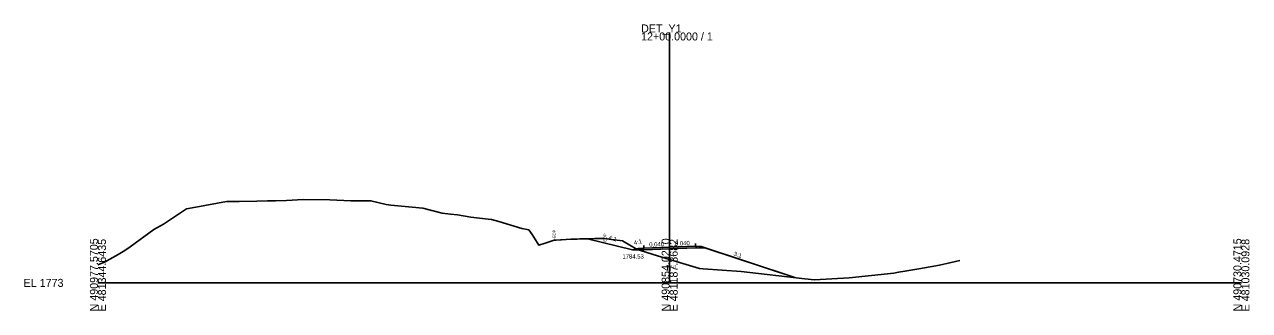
# Model space of a CAD drawing. Extents: x -26 to 403, y -10 to 3149.
# Drawn here: x -25.7 to 402.8, y 1990.3 to 2090.6 of the extents above; entities that cross this region are included whole.
import ezdxf

# ---------------------------------------------------------------- set-up
doc = ezdxf.new("R2010")
doc.units = 0
for name, color, linetype in [('Exist Cross Section Cell', 7, 'Continuous'), ('Exist XS Center Line Elevation Label', 7, 'Continuous'), ('Exist XS Ground Line', 7, 'Continuous'), ('Prop XS Ditch Slope Text', 7, 'Continuous'), ('Prop XS Ditch Standard Text', 7, 'Continuous'), ('Prop XS Dump Level', 7, 'Continuous'), ('Prop XS EOT Tick Mark', 7, 'Continuous'), ('Prop XS Finish Grade', 7, 'Continuous'), ('Prop XS Finish Grade Earthwork', 7, 'Continuous'), ('Prop XS Finish Grade Pavement', 7, 'Continuous'), ('Prop XS Pvmt Edge Slope', 7, 'Continuous'), ('Prop XS SE Text', 7, 'Continuous'), ('Prop XS Side Slope Text', 7, 'Continuous'), ('Prop XS Subgrade Earthwork', 7, 'Continuous'), ('Scratch_Level_3', 7, 'Continuous'), ('Scratch_Level_4', 7, 'Continuous')]:
    doc.layers.add(name, color=color, linetype=linetype)

msp = doc.modelspace()

# ---------------------------------------------------------------- linework, layer by layer
at = {"layer": 'Exist Cross Section Cell'}
for p, q in [((200, 2000), (200, 2087.75)), ((0, 2000), (200, 2000)), ((200, 2000), (400, 2000))]:
    msp.add_line(p, q, dxfattribs=at)
at = {"layer": 'Exist XS Ground Line'}
msp.add_lwpolyline([(0, 2006.28), (2.28, 2007.28), (7.03, 2009.95), (9.41, 2011.4), (11.27, 2012.6), (19.58, 2018.69), (22.95, 2020.54), (30.95, 2025.93), (34.2, 2026.49), (45.02, 2028.55), (49.43, 2028.56), (55.61, 2028.69), (59.27, 2028.73), (62.15, 2028.78), (65.92, 2028.92), (71.79, 2029.25), (81.07, 2029.15), (88.47, 2028.7), (95.47, 2028.8), (100.83, 2027.49), (102.48, 2027.18), (113.65, 2026.23), (120.37, 2024.48), (123.38, 2024.09), (125.74, 2023.79), (130.5, 2022.97), (136.56, 2022.36), (137.63, 2022.23), (140.27, 2021.5), (148.31, 2019.11), (150.7, 2018.56), (151.93, 2017.01), (154.23, 2013.18), (156.42, 2013.95), (159.61, 2014.91), (160.02, 2014.95), (160.34, 2014.98), (161.76, 2015.07), (162.2, 2015.1), (163.8, 2015.18), (165.4, 2015.26), (165.81, 2015.27), (167.69, 2015.35), (168.61, 2015.38), (169.84, 2015.41), (171.73, 2015.48), (173.81, 2015.54), (174.91, 2015.55), (177.35, 2015.57), (179.71, 2015.21), (183.48, 2014.68), (188.06, 2012.09), (189.08, 2011.55), (194.18, 2010), (200, 2008.21), (210.4, 2005.01), (211.68, 2004.92), (225.06, 2004.01), (247.27, 2001.43), (250.61, 2001.02), (262.81, 2001.76), (278.37, 2003.46), (280.09, 2003.72), (282.28, 2004.1), (287.21, 2004.97), (291.09, 2005.61), (294.34, 2006.25), (298.47, 2007.14), (301.46, 2007.81)], dxfattribs=at)
at = {"layer": 'Prop XS Dump Level'}
for p, q in [((191, 2012.11), (200, 2012.47)), ((200, 2012.47), (209, 2012.83))]:
    msp.add_line(p, q, dxfattribs=at)
at = {"layer": 'Prop XS EOT Tick Mark'}
for p, q in [((191, 2012.11), (191, 2013.11)), ((209, 2012.83), (209, 2013.83))]:
    msp.add_line(p, q, dxfattribs=at)
at = {"layer": 'Prop XS Finish Grade'}
for p, q in [((189, 2012.03), (187, 2011.53)), ((191, 2012.11), (189, 2012.03)), ((209, 2012.83), (211, 2012.75)), ((211, 2012.75), (212.6, 2012.22))]:
    msp.add_line(p, q, dxfattribs=at)
at = {"layer": 'Prop XS Finish Grade Earthwork'}
for p, q in [((187, 2011.53), (171.28, 2015.46)), ((212.6, 2012.22), (243.74, 2001.84))]:
    msp.add_line(p, q, dxfattribs=at)
at = {"layer": 'Prop XS Finish Grade Pavement'}
for p, q in [((191, 2012.11), (200, 2012.47)), ((200, 2012.47), (209, 2012.83))]:
    msp.add_line(p, q, dxfattribs=at)
at = {"layer": 'Prop XS Pvmt Edge Slope'}
for p, q in [((191, 2012.11), (190.44, 2011.55)), ((209, 2012.83), (209.55, 2012.28))]:
    msp.add_line(p, q, dxfattribs=at)
at = {"layer": 'Prop XS Subgrade Earthwork'}
for p, q in [((190.44, 2011.55), (187, 2011.53)), ((191, 2011.57), (190.44, 2011.55)), ((200, 2011.93), (191, 2011.57)), ((209, 2012.29), (200, 2011.93)), ((209, 2012.29), (212.6, 2012.22))]:
    msp.add_line(p, q, dxfattribs=at)
at = {"layer": 'Scratch_Level_4'}
for p, q in [((187, 2011.53), (171.28, 2015.46)), ((189, 2012.03), (187, 2011.53)), ((189, 2012.03), (189.91, 2012.07)), ((191, 2012.11), (189.91, 2012.07)), ((191, 2012.11), (200, 2012.47)), ((200, 2012.47), (209, 2012.83)), ((209, 2012.83), (210.06, 2012.79)), ((210.06, 2012.79), (211, 2012.75)), ((211, 2012.75), (243.74, 2001.84))]:
    msp.add_line(p, q, dxfattribs=at)

# ---------------------------------------------------------------- texts
at = {"layer": 'Exist Cross Section Cell'}
for s, p in [('12+00.0000 / 1', (190, 2084.95)), ('DET_Y1', (190, 2087.75)), ('EL 1773', (-26, 1998.6))]:
    msp.add_text(s, height=2.8, dxfattribs=at).set_placement(p)
for s, p in [('N 490977.5705', (0, 1990)), ('E 481344.6435', (2.8, 1990)), ('N 490854.0210', (200, 1990)), ('E 481187.3682', (202.8, 1990)), ('N 490730.4715', (400, 1990)), ('E 481030.0928', (402.8, 1990))]:
    msp.add_text(s, height=2.8, rotation=90, dxfattribs=at).set_placement(p)
at = {"layer": 'Exist XS Center Line Elevation Label'}
msp.add_text('1781.21', height=0.75, dxfattribs=at).set_placement((198.57, 2005.46))
at = {"layer": 'Prop XS Ditch Slope Text'}
msp.add_text('4:1', height=1.5, rotation=14.0362, dxfattribs=at).set_placement((187.64, 2013.23))
at = {"layer": 'Prop XS Ditch Standard Text'}
msp.add_text('1784.53', height=1.5, dxfattribs=at).set_placement((183.47, 2008.53))
at = {"layer": 'Prop XS SE Text'}
for p in [(192.88, 2012.68), (201.88, 2013.04)]:
    msp.add_text('0.040', height=1.5, rotation=2.2906, dxfattribs=at).set_placement(p)
at = {"layer": 'Prop XS Side Slope Text'}
for s, rotation, p in [('4:1', 345.9638, (178.47, 2015.21)), ('3:1', 341.5651, (222.25, 2009.61))]:
    msp.add_text(s, height=1.5, rotation=rotation, dxfattribs=at).set_placement(p)
at = {"layer": 'Scratch_Level_3'}
for p in [(160.11, 2015.23), (177.85, 2013.94)]:
    msp.add_text('-EOP', height=1, rotation=90, dxfattribs=at).set_placement(p)

doc.saveas('drawing.dxf')
